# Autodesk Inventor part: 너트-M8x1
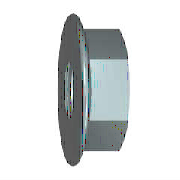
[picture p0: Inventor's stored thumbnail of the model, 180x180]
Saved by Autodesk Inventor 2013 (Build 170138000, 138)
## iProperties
Created: 2015-12
Part Number: 너트-M8x1
Material: 스테인리스강
Description: 플랜지붙이 6각 너트 - 일반 스레드
Document SubType Name: Modeling
Standard: ISO 4161
Designer: mdu
Standard Revision: 2판 1999-03-15
Standards Organization: ISO
Language: ko-KR
Size Designation: M8
Categories: <MemberInstance><Categories><Category DisplayName="조임쇠" InternalName="e4da775c-781d-43d5-af7c-5136215cf5a6" Mnemonic="FSTN"><Category DisplayName="너트" InternalN
Density: 8.08 g/cm^3
Mass: 9.03298 g
Surface Area: 8.90186 cm^2
Volume: 1.11794 cm^3
Author: mdu
IsCustomPart: 1
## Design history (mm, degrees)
sketch "스케치1"
  geometry: L1 (-1.844, 0)-(9.641, 0) reference; L2 (3.107, 6.5)-(2.288, 8.257); L3 (3.107, 6.5)-(8, 6.5); L4 (8, 6.5)-(8, 0); L5 (3.107, 6.5)-(3.107, 0); L6 (0, -1.835)-(0, 11.01) reference; A1 r 1.2 centre (1.2, 7.75) between (2.288, 8.257) and (0, 7.75); 1 further point
  constraints: 8 end point, 3 point on line, 2 perpendicular, 2 point on circle, 2 tangent, 1 centre point, 1 parallel
  dimensions: "d2" = 13 diameter of L3 L1 (= SW); "d4" = 17.9 dimension on A1 L1 (= LADI); "d5" = 1.2 radius of A1 (= PHH); "d15" = 8 distance between parallel lines of L4 L6 (= KOH); "d16" = 25 deg angle of L6 L2 (= KEWI)
revolve "링" sketch "스케치1" stored, may be unused: angle "d8" = 90 deg
sketch "스케치2"
  geometry: L1 (-6.5, -3.753)-(-6.5, 3.753); L2 (-6.5, 3.753)-(0, 7.506); L3 (0, 7.506)-(6.5, 3.753); L4 (6.5, 3.753)-(6.5, -3.753); L5 (6.5, -3.753)-(0, -7.506); L6 (0, -7.506)-(-6.5, -3.753); C1 r 4.9 at (0, 0); C2 r 7.75 at (0, 0) reference; 1 further point
  constraints: 12 end point, 1 centre point, 1 coincident, 1 vertical, 11 other
  dimensions: "d6" = 15.01111 distance of L5.end L2.end (= 1.1547 x SW)
extrude "본체" join sketch "스케치2" distance "d7" = 8 (= KOH); taper "d9" = 0 deg
sketch "스케치3"
  geometry: L1 (2.638, 7.506)-(8, 7.506) reference; L2 (8, 3.753)-(8, 7.506) reference; L3 (0, -7.75)-(0, 7.75) reference; L4 (-1.6, 0)-(9.6, 0) reference; L5 (7.419, 7.506)-(8, 6.5)
  constraints: 2 end point, 2 point on line
  dimensions: "d10" = 30 deg angle of L2 L5 (= ANG1); "d11" = 13 diameter of L5.end L4 (= SW0)
revolve "모따기1" sketch "스케치3" stored, may be unused: angle "d24" = 90 deg
sketch "스케치4"
  geometry: C1 r 7.75 at (0, 0) reference; 1 further point
  constraints: 1 coincident
hole "스레드" sketch "스케치4" at (0, 0) diameter "d25" = 6.647; stored, may be unused: countersink angle "d29" = 82 deg, drill point angle "d31" = 118 deg; dims "d26" = 6, "d27" = 4, "d28" = 2, "d30" = 8
workaxis "Work Axis1"
workplane "Work Plane1"
body "Solid1"
chamfer "모따기2" distance "d12" = 0.67658 (= -0.5 x GD1 + 0.5 x NND); stored, may be unused: angle "d13" = 30 deg, second distance "d46" = 0.67658 (= -0.5 x GD1 + 0.5 x NND)
chamfer "모따기3" distance "d51" = 0.67658 (= -0.5 x GD1 + 0.5 x NND); stored, may be unused: second distance "d52" = 2, angle "d53" = 45 deg
other parameters: "ANG1" = 30 deg [user parameter; used in 1 equation term], "KEWI" = 25 deg [user parameter; used in 1 equation term], "NND" = 8 [user parameter; used in 4 equation terms], "LADI" = 17.9 [user parameter; used in 2 equation terms], "SW" = 13 [user parameter; used in 3 equation terms], "PHH" = 1.2 [user parameter; used in 3 equation terms], "KOH" = 8 (= NND) [user parameter; used in 2 equation terms], "SW0" = 13 [user parameter; used in 1 equation term], "GD1" = 6.64684 (computed from THREADDIA, PTC, TOA) [user parameter; used in 3 equation terms], "d1" = 17.9 (= LADI), "d3" = 1.2 (= PHH), "d45" = 0, "d47" = 0, "d49" = 0, "d54" = 0, "GUL" = 0.67658 (= 0.541266 x PTC) [user parameter], "TPU" = 8 (computed from PTC) [user parameter], "RR" = 1.2 (= PHH) [user parameter], "THREADDIA" = 8 [user parameter; used in 1 equation term], "TOA" = 30 deg [user parameter; used in 1 equation term], "PTC" = 1.25 [user parameter; used in 4 equation terms], "GAL" = 0.67658 (= 0.541266 x PTC) [user parameter], "E0" = 15.015 (= 1.155 x SW) [user parameter]
